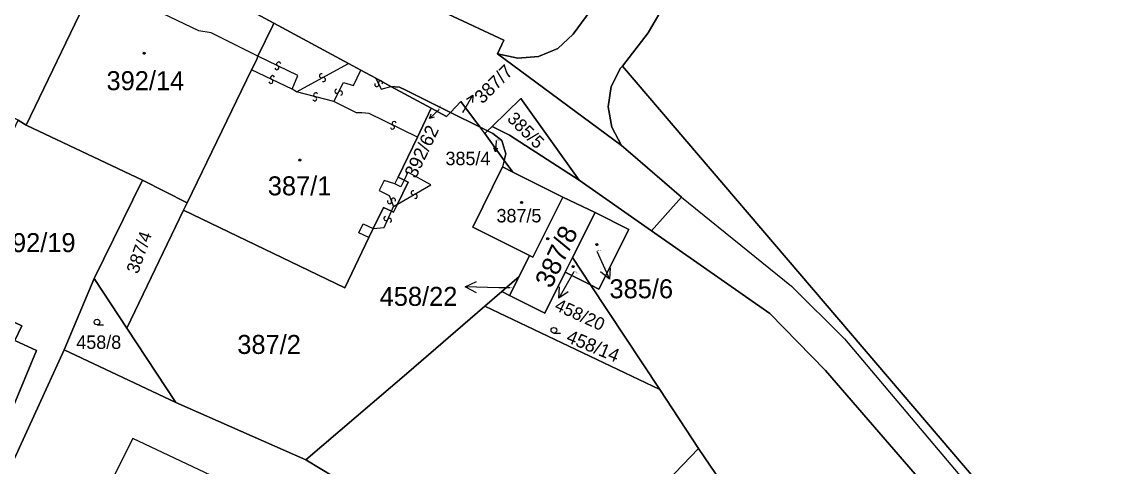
# Model space of a CAD drawing. Extents: x -600309 to -598967, y -1161267 to -1160292.
# Drawn here: x -599873.6 to -599774.9, y -1160726.6 to -1160686.8 of the extents above; entities that cross this region are included whole.
import ezdxf

# ---------------------------------------------------------------- set-up
doc = ezdxf.new("R2010")
doc.units = 0
for name, color, linetype in [('Level 1', 7, 'Continuous'), ('Level 13', 7, 'Continuous'), ('Level 3', 7, 'Continuous'), ('Level 4', 7, 'Continuous'), ('Level 5', 7, 'Continuous'), ('Level 57', 7, 'Continuous'), ('Level 60', 7, 'Continuous')]:
    doc.layers.add(name, color=color, linetype=linetype)

msp = doc.modelspace()

# ---------------------------------------------------------------- linework, layer by layer
at = {"layer": 'Level 1'}
for points in [[(-599821.86, -1160629.51), (-599815.58, -1160629.35), (-599804.26, -1160631.19), (-599801.28, -1160631.35), (-599798.3, -1160631.21), (-599797.68, -1160634.14), (-599801.75, -1160635.69), (-599805.53, -1160637.83), (-599809.07, -1160640.38), (-599812.31, -1160643.29), (-599815.14, -1160646.61), (-599817.45, -1160650.31), (-599818.45, -1160652.61), (-599819.04, -1160655.05), (-599819.17, -1160659.59), (-599818.68, -1160676.44), (-599818.99, -1160678.9), (-599819.95, -1160681.18), (-599821.96, -1160684.64), (-599824.31, -1160687.84), (-599825.67, -1160689.11), (-599827.4, -1160689.83), (-599829.25, -1160689.99), (-599831.07, -1160689.61)], [(-599819.89, -1160690.7), (-599817.59, -1160687.73), (-599815.59, -1160684.25), (-599814.41, -1160681.85), (-599813.68, -1160679.27), (-599813.45, -1160676.6), (-599813.94, -1160658.58), (-599813.77, -1160655.61), (-599812.8, -1160652.81), (-599810.34, -1160649.2), (-599807.36, -1160646.03), (-599803.9, -1160643.37), (-599800.14, -1160641.16), (-599796.14, -1160639.42), (-599793.6, -1160646.16), (-599788.04, -1160648.42), (-599782.28, -1160650.12), (-599780.36, -1160650.61), (-599774.96, -1160651.48), (-599769.49, -1160651.71)], [(-599873.24, -1160695.98), (-599867.31, -1160683.63)], [(-599851.08, -1160686.85), (-599856.56, -1160683.88)], [(-599831.07, -1160689.61), (-599830.51, -1160688.38), (-599835.94, -1160685.83)], [(-599851.08, -1160686.85), (-599851.17, -1160687.07), (-599852.51, -1160689.81)], [(-599851.08, -1160686.85), (-599844.4, -1160690.46)], [(-599831.07, -1160689.61), (-599819.97, -1160697.81)], [(-599852.51, -1160689.81), (-599852.59, -1160690.1), (-599853.09, -1160691.02)], [(-599844.4, -1160690.46), (-599843.3, -1160691.06)], [(-599819.97, -1160697.81), (-599820.83, -1160696.17), (-599821.16, -1160694.35), (-599820.89, -1160692.52), (-599820.06, -1160690.89), (-599819.89, -1160690.7)], [(-599738.79, -1160751.73), (-599783.62, -1160733.18), (-599819.89, -1160690.7)], [(-599858.83, -1160702.92), (-599853.09, -1160691.02)], [(-599841.94, -1160691.79), (-599843.3, -1160691.06)], [(-599841.94, -1160691.79), (-599840.62, -1160692.51)], [(-599836.99, -1160694.47), (-599840.62, -1160692.51)], [(-599840.62, -1160692.51), (-599839.85, -1160692.58), (-599839.28, -1160692.84), (-599835.27, -1160694.84)], [(-599823.77, -1160700.91), (-599828.99, -1160693.59), (-599831.56, -1160696.11)], [(-599836.99, -1160694.47), (-599838.23, -1160697.06)], [(-599836.99, -1160694.47), (-599835.62, -1160695.21), (-599835.27, -1160694.84)], [(-599835.27, -1160694.84), (-599834.34, -1160693.86), (-599833.3, -1160695.26), (-599832.63, -1160696.16)], [(-599873.24, -1160695.98), (-599873.96, -1160695.54)], [(-599835.27, -1160694.84), (-599832.63, -1160696.16)], [(-599862.84, -1160700.9), (-599873.24, -1160695.98)], [(-599832.63, -1160696.16), (-599831.95, -1160696.5)], [(-599832.2, -1160696.74), (-599831.95, -1160696.5)], [(-599831.56, -1160696.11), (-599831.95, -1160696.5)], [(-599831.95, -1160696.5), (-599831.49, -1160696.73), (-599830.68, -1160697.35), (-599830.31, -1160698.54), (-599830.46, -1160699.14)], [(-599831.56, -1160696.11), (-599829.99, -1160696.88), (-599823.77, -1160700.91)], [(-599839.96, -1160700.64), (-599838.23, -1160697.06)], [(-599832.2, -1160696.74), (-599830.46, -1160699.14)], [(-599819.97, -1160697.81), (-599819.16, -1160698.48), (-599814.62, -1160702.42)], [(-599829.7, -1160700.18), (-599830.46, -1160699.14)], [(-599830.61, -1160699.72), (-599833.28, -1160705.12), (-599828.21, -1160707.64)], [(-599829.7, -1160700.18), (-599830.61, -1160699.72)], [(-599825.22, -1160702.43), (-599829.7, -1160700.18)], [(-599867.16, -1160709.69), (-599862.84, -1160700.9)], [(-599862.84, -1160700.9), (-599858.83, -1160702.92)], [(-599840.02, -1160703.06), (-599839.06, -1160701.08), (-599839.43, -1160700.9)], [(-599839.96, -1160700.64), (-599839.43, -1160700.9)], [(-599823.77, -1160700.91), (-599817.3, -1160705.43)], [(-599828.21, -1160707.64), (-599827.91, -1160707.79), (-599826.39, -1160704.75), (-599825.22, -1160702.43)], [(-599825.22, -1160702.43), (-599822.34, -1160703.8)], [(-599817.3, -1160705.43), (-599814.62, -1160702.42)], [(-599859.16, -1160703.6), (-599858.83, -1160702.92)], [(-599840.56, -1160703.69), (-599841.27, -1160703.34), (-599842.18, -1160705.23)], [(-599840.56, -1160703.69), (-599840.37, -1160703.78), (-599840.02, -1160703.06)], [(-599864.24, -1160714.13), (-599859.16, -1160703.6)], [(-599859.16, -1160703.6), (-599844.74, -1160710.55), (-599842.57, -1160706.04)], [(-599824.36, -1160707.83), (-599822.34, -1160703.8)], [(-599822.34, -1160703.8), (-599819.31, -1160705.32), (-599821.99, -1160710.66), (-599822.74, -1160710.28)], [(-599842.57, -1160706.04), (-599842.18, -1160705.23)], [(-599790.83, -1160730.52), (-599801.71, -1160717.92), (-599806.7, -1160712.83), (-599817.3, -1160705.43)], [(-599828.21, -1160707.64), (-599829.14, -1160709.51)], [(-599825.02, -1160709.14), (-599824.36, -1160707.83)], [(-599822.74, -1160710.28), (-599824.36, -1160707.83)], [(-599830.68, -1160710.86), (-599829.78, -1160710.08), (-599829.14, -1160709.51)], [(-599825.02, -1160709.14), (-599826.84, -1160712.79), (-599829.99, -1160711.21)], [(-599829.14, -1160709.51), (-599829.99, -1160711.21)], [(-599822.74, -1160710.28), (-599825.02, -1160709.14)], [(-599886.51, -1160722.26), (-599878.19, -1160726.15), (-599875.71, -1160720.83), (-599874.49, -1160721.4), (-599872.3, -1160716.15), (-599874.24, -1160715.24), (-599873.63, -1160713.93), (-599880.98, -1160710.48)], [(-599867.16, -1160709.69), (-599869.83, -1160716.08)], [(-599864.24, -1160714.13), (-599867.16, -1160709.69)], [(-599816.56, -1160719.64), (-599822.74, -1160710.28)], [(-599830.68, -1160710.86), (-599832.19, -1160712.17)], [(-599829.99, -1160711.21), (-599830.68, -1160710.86)], [(-599848.21, -1160725.92), (-599839.2, -1160718.23), (-599832.19, -1160712.17)], [(-599832.19, -1160712.17), (-599816.56, -1160719.64)], [(-599859.84, -1160720.79), (-599864.24, -1160714.13)], [(-599869.83, -1160716.08), (-599876.1, -1160729.71)], [(-599869.83, -1160716.08), (-599859.84, -1160720.79)], [(-599813.09, -1160724.9), (-599816.56, -1160719.64)], [(-599848.21, -1160725.92), (-599859.84, -1160720.79)], [(-599813.09, -1160724.9), (-599836.29, -1160749.09), (-599847.63, -1160768.09), (-599866.32, -1160812.77)], [(-599807.63, -1160732.93), (-599813.09, -1160724.9)], [(-599845.64, -1160727.48), (-599848.21, -1160725.92)]]:
    msp.add_lwpolyline(points, dxfattribs=at)
at = {"layer": 'Level 13'}
for centre, start, end in [((-599850.812, -1160690.835), 191.64831, 63.7463), ((-599850.649, -1160690.505), 11.43385, 244.02385), ((-599851.19, -1160691.734), 11.48146, 244.07146), ((-599846.817, -1160691.567), 66.06067, 298.15866), ((-599846.642, -1160691.892), 245.84621, 118.43621), ((-599851.351, -1160692.065), 191.69592, 63.79391), ((-599841.876, -1160692.35), 153.01014, 25.60014), ((-599841.543, -1160692.191), 333.2246, 205.32259), ((-599847.428, -1160693.618), 202.97488, 75.07288), ((-599847.333, -1160693.262), 22.76042, 255.35043), ((-599845.444, -1160692.936), 100.94186, 333.03986), ((-599845.116, -1160693.103), 280.72741, 153.31741), ((-599840.308, -1160695.835), 11.12619, 243.71619), ((-599840.472, -1160696.165), 191.34065, 63.43865), ((-599840.378, -1160702.695), 328.67852, 200.77651), ((-599838.611, -1160702.03), 67.56956, 299.66756), ((-599838.428, -1160702.349), 247.35511, 119.94511), ((-599840.722, -1160702.826), 148.46406, 21.05406), ((-599841.057, -1160704.342), 102.89901, 334.99701), ((-599840.723, -1160704.497), 282.68456, 155.27456)]:
    msp.add_arc(centre, 0.184, start, end, dxfattribs=at)
at = {"layer": 'Level 3'}
for points in [[(-599852.51, -1160689.81), (-599856.7, -1160687.73), (-599857.78, -1160687.55), (-599862.99, -1160685.07), (-599863.79, -1160685.37), (-599867.31, -1160683.63)], [(-599849.45, -1160692.77), (-599848.94, -1160691.53), (-599852.51, -1160689.81)], [(-599849.06, -1160693.01), (-599844.4, -1160690.46)], [(-599849.45, -1160692.77), (-599853.09, -1160691.02)], [(-599845.71, -1160693.87), (-599844.86, -1160692.16), (-599843.96, -1160692.44), (-599843.3, -1160691.06)], [(-599841.94, -1160691.79), (-599841.47, -1160692.76), (-599840.62, -1160692.51)], [(-599849.06, -1160693.01), (-599849.45, -1160692.77)], [(-599845.71, -1160693.87), (-599849.06, -1160693.01)], [(-599838.23, -1160697.06), (-599842.55, -1160694.95), (-599843.22, -1160694.88), (-599843.67, -1160694.88), (-599845.71, -1160693.87)], [(-599832.2, -1160696.74), (-599832.63, -1160696.16)], [(-599830.46, -1160699.14), (-599830.61, -1160699.72)], [(-599840.02, -1160703.06), (-599837.03, -1160701.32), (-599839.08, -1160700.19), (-599839.43, -1160700.9)], [(-599840.25, -1160701.23), (-599841.22, -1160700.92), (-599841.65, -1160701.82), (-599840.75, -1160702.26), (-599840.36, -1160703.26)], [(-599840.25, -1160701.23), (-599839.96, -1160700.64)], [(-599839.43, -1160700.9), (-599839.73, -1160701.5), (-599840.25, -1160701.23)], [(-599814.62, -1160702.42), (-599804.76, -1160710.4), (-599800.02, -1160715.09), (-599786.17, -1160731.52), (-599782.68, -1160734.74), (-599777.96, -1160737.07), (-599739.29, -1160753.24)], [(-599840.56, -1160703.69), (-599840.36, -1160703.26)], [(-599840.36, -1160703.26), (-599840.02, -1160703.06)], [(-599842.18, -1160705.23), (-599841.22, -1160705.14), (-599840.56, -1160703.69)], [(-599842.57, -1160706.04), (-599843.47, -1160705.61), (-599843.08, -1160704.8), (-599842.18, -1160705.23)], [(-599847.6, -1160731.63), (-599863.69, -1160724.03), (-599868.38, -1160733.35)]]:
    msp.add_lwpolyline(points, dxfattribs=at)
at = {"layer": 'Level 5'}
for p, q in [((-599866.9, -1160713.85), (-599866.305, -1160713.85)), ((-599826.02, -1160714.59), (-599825.425, -1160714.59))]:
    msp.add_line(p, q, dxfattribs=at)
for centre, radius in [((-599862.69, -1160689.55), 0.09), ((-599862.69, -1160689.55), 0.0521), ((-599848.76, -1160699.1), 0.09), ((-599848.76, -1160699.1), 0.0521), ((-599828.91, -1160702.89), 0.09), ((-599828.91, -1160702.89), 0.0521), ((-599826.58, -1160706.14), 0.09), ((-599826.58, -1160706.14), 0.0521), ((-599822.19, -1160706.67), 0.09), ((-599822.19, -1160706.67), 0.0521), ((-599824.31, -1160708.64), 0.09), ((-599824.31, -1160708.64), 0.0521), ((-599866.9, -1160713.595), 0.255), ((-599826.02, -1160714.335), 0.255)]:
    msp.add_circle(centre, radius, dxfattribs=at)
at = {"layer": 'Level 57'}
for p, q in [((-599834.18, -1160694.85), (-599833.269, -1160693.291)), ((-599836.29, -1160694.58), (-599837.14, -1160695.38)), ((-599831.2, -1160697.36), (-599831.24, -1160698.36)), ((-599822.17, -1160707.24), (-599821.051, -1160709.77)), ((-599824.23, -1160709.11), (-599825.578, -1160711.446)), ((-599830.949, -1160710.525), (-599833.948, -1160710.45)), ((-599829.95, -1160710.55), (-599830.949, -1160710.525))]:
    msp.add_line(p, q, dxfattribs=at)
for points in [[(-599833.832, -1160693.659), (-599833.269, -1160693.291), (-599833.313, -1160693.963)], [(-599836.723, -1160695.255), (-599837.14, -1160695.38), (-599836.99, -1160694.972)], [(-599831.06, -1160698.033), (-599831.24, -1160698.36), (-599831.393, -1160698.02)], [(-599821.002, -1160708.74), (-599821.051, -1160709.77), (-599821.846, -1160709.113)], [(-599832.961, -1160710.975), (-599833.948, -1160710.45), (-599832.936, -1160709.975)], [(-599824.74, -1160710.892), (-599825.578, -1160711.446), (-599825.518, -1160710.442)]]:
    msp.add_lwpolyline(points, dxfattribs=at)
at = {"layer": 'Level 60'}
for points in [[(-599738.79, -1160751.73), (-599783.62, -1160733.18), (-599819.89, -1160690.7), (-599817.59, -1160687.73), (-599815.59, -1160684.25), (-599814.41, -1160681.85), (-599813.68, -1160679.27), (-599813.45, -1160676.6), (-599813.94, -1160658.58), (-599813.77, -1160655.61), (-599812.8, -1160652.81), (-599810.34, -1160649.2), (-599807.36, -1160646.03), (-599803.9, -1160643.37), (-599800.14, -1160641.16), (-599796.14, -1160639.42), (-599793.6, -1160646.16), (-599788.04, -1160648.42), (-599782.28, -1160650.12), (-599780.36, -1160650.61), (-599774.96, -1160651.48), (-599769.49, -1160651.71)], [(-599835.94, -1160685.83), (-599830.51, -1160688.38), (-599831.07, -1160689.61), (-599819.97, -1160697.81), (-599819.16, -1160698.48), (-599814.62, -1160702.42), (-599817.3, -1160705.43), (-599823.77, -1160700.91), (-599828.99, -1160693.59), (-599831.56, -1160696.11), (-599831.95, -1160696.5), (-599832.63, -1160696.16), (-599833.3, -1160695.26), (-599834.34, -1160693.86), (-599835.27, -1160694.84), (-599839.28, -1160692.84), (-599839.85, -1160692.58), (-599840.62, -1160692.51), (-599841.94, -1160691.79), (-599843.3, -1160691.06), (-599844.4, -1160690.46), (-599851.08, -1160686.85), (-599856.56, -1160683.88)], [(-599821.96, -1160684.64), (-599824.31, -1160687.84), (-599825.67, -1160689.11), (-599827.4, -1160689.83), (-599829.25, -1160689.99), (-599831.07, -1160689.61), (-599830.51, -1160688.38), (-599835.94, -1160685.83)], [(-599815.59, -1160684.25), (-599817.59, -1160687.73), (-599819.89, -1160690.7), (-599820.06, -1160690.89), (-599820.89, -1160692.52), (-599821.16, -1160694.35), (-599820.83, -1160696.17), (-599819.97, -1160697.81), (-599831.07, -1160689.61), (-599829.25, -1160689.99), (-599827.4, -1160689.83), (-599825.67, -1160689.11), (-599824.31, -1160687.84), (-599821.96, -1160684.64)], [(-599807.63, -1160732.93), (-599813.09, -1160724.9), (-599816.56, -1160719.64), (-599822.74, -1160710.28), (-599821.99, -1160710.66), (-599819.31, -1160705.32), (-599822.34, -1160703.8), (-599825.22, -1160702.43), (-599829.7, -1160700.18), (-599830.46, -1160699.14), (-599830.31, -1160698.54), (-599830.68, -1160697.35), (-599831.49, -1160696.73), (-599831.95, -1160696.5), (-599831.56, -1160696.11), (-599829.99, -1160696.88), (-599823.77, -1160700.91), (-599817.3, -1160705.43), (-599806.7, -1160712.83), (-599801.71, -1160717.92), (-599790.83, -1160730.52)], [(-599845.64, -1160727.48), (-599848.21, -1160725.92), (-599839.2, -1160718.23), (-599832.19, -1160712.17), (-599816.56, -1160719.64), (-599813.09, -1160724.9), (-599836.29, -1160749.09)]]:
    msp.add_lwpolyline(points, dxfattribs=at)
for points in [[(-599873.24, -1160695.98), (-599873.96, -1160695.54), (-599879.75, -1160692.83), (-599885.49, -1160690.13), (-599887.65, -1160689.03), (-599881.63, -1160676.54), (-599881.39, -1160676.04), (-599879.71, -1160672.56), (-599865.33, -1160679.59), (-599866.77, -1160682.57), (-599867.31, -1160683.63)], [(-599858.83, -1160702.92), (-599862.84, -1160700.9), (-599873.24, -1160695.98), (-599867.31, -1160683.63), (-599866.77, -1160682.57), (-599865.33, -1160679.59), (-599856.56, -1160683.88), (-599851.08, -1160686.85), (-599851.17, -1160687.07), (-599852.51, -1160689.81), (-599852.59, -1160690.1), (-599853.09, -1160691.02)], [(-599844.74, -1160710.55), (-599859.16, -1160703.6), (-599858.83, -1160702.92), (-599853.09, -1160691.02), (-599852.59, -1160690.1), (-599852.51, -1160689.81), (-599851.17, -1160687.07), (-599851.08, -1160686.85), (-599844.4, -1160690.46), (-599843.3, -1160691.06), (-599841.94, -1160691.79), (-599840.62, -1160692.51), (-599836.99, -1160694.47), (-599838.23, -1160697.06), (-599839.96, -1160700.64), (-599839.43, -1160700.9), (-599839.06, -1160701.08), (-599840.02, -1160703.06), (-599840.37, -1160703.78), (-599840.56, -1160703.69), (-599841.27, -1160703.34), (-599842.18, -1160705.23), (-599842.57, -1160706.04)], [(-599738.79, -1160751.73), (-599739.29, -1160753.24), (-599730.92, -1160756.04), (-599734.97, -1160757.76), (-599734.63, -1160758.55), (-599739.76, -1160756.17), (-599742.8, -1160755), (-599779.99, -1160739.86), (-599783.33, -1160737.73), (-599788.05, -1160733.72), (-599790.83, -1160730.52), (-599801.71, -1160717.92), (-599806.7, -1160712.83), (-599817.3, -1160705.43), (-599814.62, -1160702.42), (-599819.16, -1160698.48), (-599819.97, -1160697.81), (-599820.83, -1160696.17), (-599821.16, -1160694.35), (-599820.89, -1160692.52), (-599820.06, -1160690.89), (-599819.89, -1160690.7), (-599783.62, -1160733.18)], [(-599835.62, -1160695.21), (-599836.99, -1160694.47), (-599840.62, -1160692.51), (-599839.85, -1160692.58), (-599839.28, -1160692.84), (-599835.27, -1160694.84)], [(-599828.99, -1160693.59), (-599823.77, -1160700.91), (-599829.99, -1160696.88), (-599831.56, -1160696.11)], [(-599859.16, -1160703.6), (-599844.74, -1160710.55), (-599842.57, -1160706.04), (-599842.18, -1160705.23), (-599841.27, -1160703.34), (-599840.56, -1160703.69), (-599840.37, -1160703.78), (-599840.02, -1160703.06), (-599839.06, -1160701.08), (-599839.43, -1160700.9), (-599839.96, -1160700.64), (-599838.23, -1160697.06), (-599836.99, -1160694.47), (-599835.62, -1160695.21), (-599835.27, -1160694.84), (-599832.63, -1160696.16), (-599831.95, -1160696.5), (-599832.2, -1160696.74), (-599830.46, -1160699.14), (-599829.7, -1160700.18), (-599830.61, -1160699.72), (-599833.28, -1160705.12), (-599828.21, -1160707.64), (-599829.14, -1160709.51), (-599829.78, -1160710.08), (-599830.68, -1160710.86), (-599832.19, -1160712.17), (-599839.2, -1160718.23), (-599848.21, -1160725.92), (-599859.84, -1160720.79), (-599864.24, -1160714.13)], [(-599832.63, -1160696.16), (-599835.27, -1160694.84), (-599834.34, -1160693.86), (-599833.3, -1160695.26)], [(-599862.84, -1160700.9), (-599867.16, -1160709.69), (-599869.83, -1160716.08), (-599876.1, -1160729.71), (-599887.48, -1160724.32), (-599886.51, -1160722.26), (-599878.19, -1160726.15), (-599875.71, -1160720.83), (-599874.49, -1160721.4), (-599872.3, -1160716.15), (-599874.24, -1160715.24), (-599873.63, -1160713.93), (-599880.98, -1160710.48), (-599878.91, -1160706.08), (-599873.96, -1160695.54), (-599873.24, -1160695.98)], [(-599832.2, -1160696.74), (-599831.95, -1160696.5), (-599831.49, -1160696.73), (-599830.68, -1160697.35), (-599830.31, -1160698.54), (-599830.46, -1160699.14)], [(-599826.39, -1160704.75), (-599827.91, -1160707.79), (-599828.21, -1160707.64), (-599833.28, -1160705.12), (-599830.61, -1160699.72), (-599829.7, -1160700.18), (-599825.22, -1160702.43)], [(-599858.83, -1160702.92), (-599859.16, -1160703.6), (-599864.24, -1160714.13), (-599867.16, -1160709.69), (-599862.84, -1160700.9)], [(-599827.91, -1160707.79), (-599826.39, -1160704.75), (-599825.22, -1160702.43), (-599822.34, -1160703.8), (-599824.36, -1160707.83), (-599825.02, -1160709.14), (-599826.84, -1160712.79), (-599829.99, -1160711.21), (-599829.14, -1160709.51), (-599828.21, -1160707.64)], [(-599822.34, -1160703.8), (-599819.31, -1160705.32), (-599821.99, -1160710.66), (-599822.74, -1160710.28), (-599824.36, -1160707.83)], [(-599822.74, -1160710.28), (-599825.02, -1160709.14), (-599824.36, -1160707.83)], [(-599816.56, -1160719.64), (-599832.19, -1160712.17), (-599830.68, -1160710.86), (-599829.99, -1160711.21), (-599826.84, -1160712.79), (-599825.02, -1160709.14), (-599822.74, -1160710.28)], [(-599830.68, -1160710.86), (-599829.78, -1160710.08), (-599829.14, -1160709.51), (-599829.99, -1160711.21)], [(-599885.92, -1160721), (-599880.98, -1160710.48), (-599873.63, -1160713.93), (-599874.24, -1160715.24), (-599872.3, -1160716.15), (-599874.49, -1160721.4), (-599875.71, -1160720.83), (-599878.19, -1160726.15), (-599886.51, -1160722.26)], [(-599864.24, -1160714.13), (-599859.84, -1160720.79), (-599869.83, -1160716.08), (-599867.16, -1160709.69)], [(-599859.84, -1160720.79), (-599848.21, -1160725.92), (-599845.64, -1160727.48), (-599847.6, -1160731.63), (-599847.73, -1160731.9), (-599849.21, -1160735.05), (-599849.36, -1160735.37), (-599852.04, -1160741.05), (-599852.16, -1160741), (-599852.33, -1160740.92), (-599867.87, -1160733.59), (-599868.38, -1160733.35), (-599871.94, -1160731.67), (-599876.1, -1160729.71), (-599869.83, -1160716.08)], [(-599836.29, -1160749.09), (-599813.09, -1160724.9), (-599807.63, -1160732.93), (-599824.58, -1160752.88), (-599825.43, -1160752.89), (-599842.61, -1160783.8), (-599855.88, -1160813.72), (-599866.32, -1160812.77), (-599847.63, -1160768.09)]]:
    msp.add_lwpolyline(points, close=True, dxfattribs=at)

# ---------------------------------------------------------------- texts
at = {"layer": 'Level 4'}
for s, height, p in [('392/14', 1.7, (-599866.05, -1160692.85)), ('385/4', 0.1, (-599831.2, -1160697.36)), ('387/1', 1.7, (-599851.62, -1160702.26)), ('387/5', 1.2, (-599831.16, -1160704.68)), ('392/19', 1.7, (-599875.77, -1160707.34)), ('385/6', 0.1, (-599822.17, -1160707.24)), ('458/22', 0.1, (-599829.95, -1160710.55)), ('458/8', 1.2, (-599868.75, -1160716)), ('387/2', 1.7, (-599854.35, -1160716.45))]:
    msp.add_text(s, height=height, dxfattribs=at).set_placement(p)
for s, height, rotation, p in [('392/62', 0.1, 64.8, (-599836.29, -1160694.58)), ('387/7', 0.1, 45, (-599834.18, -1160694.85)), ('385/5', 1.14, 315.16407, (-599830.28, -1160695.49)), ('387/4', 1.14, 70.68987, (-599863.232, -1160709.347)), ('387/8', 1.7, 64.75905, (-599826.257, -1160710.665)), ('458/20', 0.1, 335.53926, (-599824.23, -1160709.11)), ('458/14', 1.2, 337.5, (-599825.01, -1160715.35))]:
    msp.add_text(s, height=height, rotation=rotation, dxfattribs=at).set_placement(p)
at = {"layer": 'Level 57'}
for s, height, rotation, p in [('387/7', 1.2, 45, (-599832.42, -1160694.14)), ('392/62', 1.2, 64.8, (-599838.368, -1160700.807)), ('458/20', 1.14, 335.53926, (-599826.051, -1160712.484))]:
    msp.add_text(s, height=height, rotation=rotation, dxfattribs=at).set_placement(p)
for s, height, p in [('385/4', 1.2, (-599835.722, -1160699.56)), ('458/22', 1.7, (-599841.612, -1160712.15)), ('385/6', 1.7, (-599821.051, -1160711.47))]:
    msp.add_text(s, height=height, dxfattribs=at).set_placement(p)

doc.saveas('drawing.dxf')
